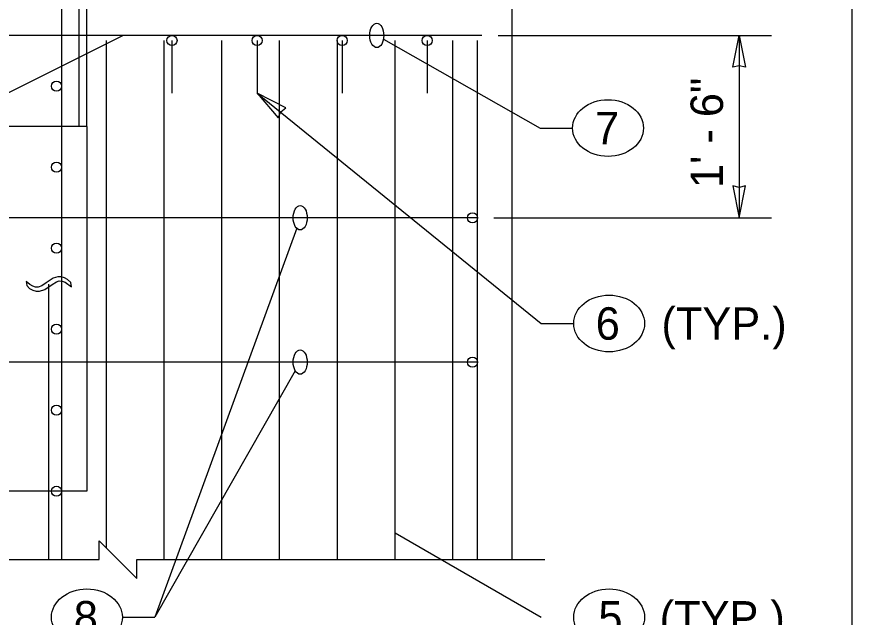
# Model space of a CAD drawing. Extents: x 99862 to 103151, y 100000 to 102076.
# Drawn here: x 102737.5 to 103150, y 100908.5 to 101205 of the extents above; entities that cross this region are included whole.
import ezdxf

# ---------------------------------------------------------------- set-up
doc = ezdxf.new("R2010")
doc.units = 0
for name, color, linetype in [('Level 10', 7, 'Continuous'), ('Level 15', 7, 'Continuous'), ('Level 2', 7, 'Continuous'), ('Level 20', 7, 'Continuous'), ('Level 60', 7, 'Continuous')]:
    doc.layers.add(name, color=color, linetype=linetype)

msp = doc.modelspace()

# ---------------------------------------------------------------- linework, layer by layer
at = {"layer": 'Level 10'}
for p, q in [((102759.67, 101247.8), (102759.67, 100936.99)), ((102397.17, 100999.36), (102789.88, 101195.71)), ((102397.17, 100999.36), (102789.88, 101195.71)), ((102967.17, 101195.71), (102602.17, 101195.71)), ((102781.82, 100942.68), (102781.82, 101193.21)), ((102810.32, 100936.99), (102810.32, 101193.21)), ((102814.17, 101193.21), (102814.17, 101167.28)), ((102814.17, 101193.21), (102814.17, 101167.28)), ((102838.82, 100936.99), (102838.82, 101193.21)), ((102856.17, 101193.21), (102856.17, 101167.28)), ((102856.17, 101193.21), (102856.17, 101167.28)), ((102867.32, 100936.99), (102867.32, 101193.21)), ((102895.82, 100936.99), (102895.82, 101193.21)), ((102898.17, 101193.21), (102898.17, 101167.28)), ((102898.17, 101193.21), (102898.17, 101167.28)), ((102924.32, 100936.99), (102924.32, 101193.21)), ((102924.32, 100936.99), (102924.32, 101193.21)), ((102940.17, 101193.21), (102940.17, 101167.28)), ((102940.17, 101193.21), (102940.17, 101167.28)), ((102952.82, 100936.99), (102952.82, 101193.21)), ((102964.98, 100936.99), (102964.98, 101193.21)), ((102964.98, 101105.71), (102615.47, 101105.71)), ((102964.98, 101105.71), (102615.47, 101105.71)), ((102753.32, 100936.99), (102753.32, 101072.99)), ((102753.32, 100936.99), (102753.32, 101072.99)), ((102964.98, 101034.46), (102472.97, 101034.46))]:
    msp.add_line(p, q, dxfattribs=at)
for centre in [(102814.17, 101193.21), (102814.17, 101193.21), (102856.17, 101193.21), (102856.17, 101193.21), (102898.17, 101193.21), (102898.17, 101193.21), (102940.17, 101193.21), (102940.17, 101193.21), (102757.17, 101170.72), (102757.17, 101170.72), (102757.17, 101130.72), (102757.17, 101130.72), (102962.48, 101105.71), (102962.48, 101105.71), (102757.17, 101090.72), (102757.17, 101090.72), (102757.17, 101050.72), (102757.17, 101050.72), (102962.48, 101034.46), (102962.48, 101034.46), (102757.17, 101010.72), (102757.17, 101010.72), (102757.17, 100970.72), (102757.17, 100970.72)]:
    msp.add_circle(centre, 2.5, dxfattribs=at)
at = {"layer": 'Level 15'}
for p, q in [((102918.55, 101193.82), (102995.91, 101150)), ((102918.55, 101193.82), (102995.91, 101150)), ((102975.17, 101195.71), (103110.17, 101195.71)), ((102975.17, 101195.71), (103110.17, 101195.71)), ((103094.17, 101195.71), (103094.17, 101105.71)), ((103094.17, 101195.71), (103094.17, 101105.71)), ((102856.17, 101167.28), (102996.46, 101053.53)), ((102856.17, 101167.28), (102996.46, 101053.53)), ((102995.91, 101150), (103011.91, 101150)), ((102995.91, 101150), (103011.91, 101150)), ((102972.98, 101105.71), (103110.17, 101105.71)), ((102972.98, 101105.71), (103110.17, 101105.71)), ((102875.73, 101100.52), (102805.67, 100908.54)), ((102875.73, 101100.52), (102805.67, 100908.54)), ((102996.46, 101053.53), (103012.46, 101053.53)), ((102996.46, 101053.53), (103012.46, 101053.53)), ((102875.03, 101030.2), (102805.67, 100908.54)), ((102875.03, 101030.2), (102805.67, 100908.54)), ((102924.32, 100950.16), (102996.46, 100908.51)), ((102924.32, 100950.16), (102996.46, 100908.51)), ((102778.21, 100936.99), (102778.21, 100946.29)), ((102778.21, 100946.29), (102796.8, 100927.7)), ((102778.21, 100936.99), (102778.21, 100946.29)), ((102778.21, 100946.29), (102796.8, 100927.7)), ((102586.13, 100936.99), (102778.21, 100936.99)), ((102586.13, 100936.99), (102778.21, 100936.99)), ((102796.8, 100927.7), (102796.8, 100936.99)), ((102796.8, 100936.99), (102998.17, 100936.99)), ((102796.8, 100927.7), (102796.8, 100936.99)), ((102796.8, 100936.99), (102998.17, 100936.99)), ((102789.67, 100908.54), (102805.67, 100908.54)), ((102789.67, 100908.54), (102805.67, 100908.54))]:
    msp.add_line(p, q, dxfattribs=at)
for points in [[(103094.17, 101195.71), (103097.26, 101179.99), (103094.17, 101180.72), (103091.09, 101179.99)], [(103094.17, 101195.71), (103097.26, 101179.99), (103094.17, 101180.72), (103091.09, 101179.99)], [(102856.17, 101167.28), (102866.57, 101155.08), (102867.91, 101157.95), (102870.4, 101159.91)], [(103094.17, 101105.71), (103097.26, 101121.44), (103094.17, 101120.71), (103091.09, 101121.44)], [(103094.17, 101105.71), (103097.26, 101121.44), (103094.17, 101120.71), (103091.09, 101121.44)]]:
    msp.add_lwpolyline(points, close=True, dxfattribs=at)
for centre in [(102915.27, 101195.71), (102915.27, 101195.71), (102877.46, 101105.71), (102877.46, 101105.71), (102877.46, 101034.46), (102877.46, 101034.46)]:
    msp.add_ellipse(centre, major_axis=(0, -6), ratio=0.57735, dxfattribs=at)
at = {"layer": 'Level 2'}
for p, q in [((102768.42, 101150.71), (102768.42, 101334.05)), ((102768.42, 101150.71), (102768.42, 101334.05)), ((102772.17, 101150.71), (102772.17, 101334.05)), ((102772.17, 101150.71), (102772.17, 101334.05)), ((102982.17, 100936.99), (102982.17, 101210.71)), ((102982.17, 100936.99), (102982.17, 101210.71)), ((102772.17, 101150.71), (102592.17, 101150.71)), ((102772.17, 101150.71), (102592.17, 101150.71)), ((102772.17, 101150.71), (102772.17, 100970.72)), ((102772.17, 101150.71), (102772.17, 100970.72)), ((102772.17, 100970.72), (102592.17, 100970.72)), ((102772.17, 100970.72), (102592.17, 100970.72))]:
    msp.add_line(p, q, dxfattribs=at)
at = {"layer": 'Level 20'}
for p, q in [((102744.03, 101072.78), (102742.16, 101074.33)), ((102742.16, 101074.33), (102742.46, 101072.23)), ((102744.03, 101072.78), (102742.16, 101074.33)), ((102742.16, 101074.33), (102742.46, 101072.23)), ((102752.12, 101073.53), (102749.98, 101072.14)), ((102752.12, 101073.53), (102749.98, 101072.14)), ((102755.5, 101075.83), (102752.12, 101073.53)), ((102755.5, 101075.83), (102752.12, 101073.53)), ((102755.09, 101072.74), (102757.12, 101074.06)), ((102755.09, 101072.74), (102757.12, 101074.06)), ((102757.86, 101076.55), (102755.5, 101075.83)), ((102757.86, 101076.55), (102755.5, 101075.83)), ((102757.12, 101074.06), (102758.55, 101074.51)), ((102757.12, 101074.06), (102758.55, 101074.51)), ((102759.52, 101076.57), (102757.86, 101076.55)), ((102759.52, 101076.57), (102757.86, 101076.55)), ((102758.55, 101074.51), (102759.97, 101074.46)), ((102758.55, 101074.51), (102759.97, 101074.46)), ((102761.08, 101076.14), (102759.52, 101076.57)), ((102761.08, 101076.14), (102759.52, 101076.57)), ((102759.97, 101074.46), (102761.52, 101073.89)), ((102759.97, 101074.46), (102761.52, 101073.89)), ((102762.61, 101075.23), (102761.08, 101076.14)), ((102762.61, 101075.23), (102761.08, 101076.14)), ((102761.52, 101073.89), (102764.49, 101071.69)), ((102761.52, 101073.89), (102764.49, 101071.69)), ((102764.19, 101073.79), (102762.61, 101075.23)), ((102764.19, 101073.79), (102762.61, 101075.23)), ((102764.49, 101071.69), (102764.19, 101073.79)), ((102764.49, 101071.69), (102764.19, 101073.79)), ((102742.46, 101072.23), (102743.88, 101070.84)), ((102742.46, 101072.23), (102743.88, 101070.84)), ((102743.88, 101070.84), (102745.41, 101069.91)), ((102743.88, 101070.84), (102745.41, 101069.91)), ((102745.52, 101071.89), (102744.03, 101072.78)), ((102745.52, 101071.89), (102744.03, 101072.78)), ((102745.41, 101069.91), (102747.05, 101069.46)), ((102745.41, 101069.91), (102747.05, 101069.46)), ((102746.83, 101071.52), (102745.52, 101071.89)), ((102746.83, 101071.52), (102745.52, 101071.89)), ((102748.16, 101071.52), (102746.83, 101071.52)), ((102748.16, 101071.52), (102746.83, 101071.52)), ((102747.05, 101069.46), (102748.81, 101069.48)), ((102747.05, 101069.46), (102748.81, 101069.48)), ((102749.98, 101072.14), (102748.16, 101071.52)), ((102749.98, 101072.14), (102748.16, 101071.52)), ((102748.81, 101069.48), (102751.4, 101070.32)), ((102748.81, 101069.48), (102751.4, 101070.32)), ((102751.4, 101070.32), (102755.09, 101072.74)), ((102751.4, 101070.32), (102755.09, 101072.74))]:
    msp.add_line(p, q, dxfattribs=at)
for centre in [(103029.41, 101150), (103029.96, 101053.53), (102772.17, 100908.54), (103029.96, 100908.51)]:
    msp.add_ellipse(centre, major_axis=(-17.5, 0), ratio=0.8, dxfattribs=at)
at = {"layer": 'Level 60'}
msp.add_line((103150, 100000), (103150, 102075), dxfattribs=at)

# ---------------------------------------------------------------- texts
at = {"layer": 'Level 20'}
for s, rotation, p in [('1\' - 6"', 90, (103086.17, 101120.38)), ('5', 360, (103024.65, 100900.51))]:
    msp.add_text(s, height=16, rotation=rotation, dxfattribs=at).set_placement(p)
for s, p in [('7', (103023.01, 101142)), ('6', (103023.35, 101045.53)), ('(TYP.)', (103055.8, 101045.53)), ('8', (102765.71, 100900.54)), ('(TYP.)', (103054.91, 100900.48))]:
    msp.add_text(s, height=16, dxfattribs=at).set_placement(p)

doc.saveas('drawing.dxf')
